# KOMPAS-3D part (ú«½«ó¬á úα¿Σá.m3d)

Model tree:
1. Эскиз:1
2. Операция выдавливания:1
     Расстояние 1 = 16
3. Эскиз:2
4. Вырезать элемент выдавливания:1
     Расстояние 1 = 14.4
5. Эскиз:3
6. Операция выдавливания:2
     Расстояние 1 = 2; Расстояние 2 = 124
7. Скругление:1
     Радиус = 5
8. Скругление:2
     Радиус = 5
9. Скругление:3
     Радиус = 5
10. Эскиз:4
11. Операция выдавливания:3
     Расстояние 1 = 5; Расстояние 2 = 115
12. Эскиз:5
13. Эскиз:6
14. Операция выдавливания:4
     Расстояние 1 = 2
15. Скругление:4
     Радиус = 3
16. Эскиз:7
17. Операция выдавливания:5
     Расстояние 1 = 0.5
